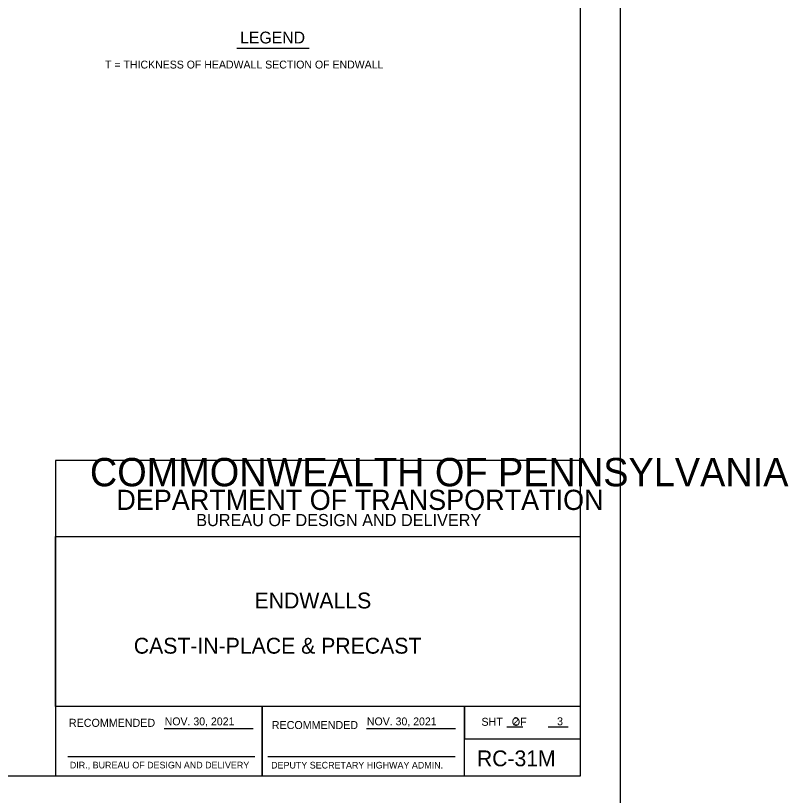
# Model space of a CAD drawing. Extents: x 638877 to 639960, y 297341 to 299123.
# Drawn here: x 639488 to 639782.3, y 297942.8 to 298239.6 of the extents above; entities that cross this region are included whole.
import ezdxf

# ---------------------------------------------------------------- set-up
doc = ezdxf.new("R2010")
doc.units = 0
for name, color, linetype in [('1', 7, 'Continuous'), ('2', 7, 'Continuous'), ('3', 7, 'Continuous'), ('PLT-BNDY', 7, 'Continuous')]:
    doc.layers.add(name, color=color, linetype=linetype)

msp = doc.modelspace()

# ---------------------------------------------------------------- linework, layer by layer
at = {"layer": '1'}
for p, q in [((639703.19, 297950.28), (639703.19, 298514.28)), ((639572.29, 298227.14), (639599.84, 298227.14)), ((639703.19, 298070.28), (639503.19, 298070.28)), ((639503.19, 298070.28), (639503.19, 297950.28)), ((639703.19, 298041.32), (639703.19, 298070.28)), ((639503.19, 297976.64), (639503.19, 298041.32)), ((639503.19, 298041.32), (639703.19, 298041.32)), ((639703.19, 297976.64), (639503.19, 297976.64)), ((639581.99, 297950.28), (639581.99, 297976.64)), ((639581.99, 297976.64), (639581.99, 297950.28)), ((639658.99, 297950.28), (639658.99, 297976.64)), ((639658.99, 297976.64), (639658.99, 297964.33)), ((639703.19, 297950.28), (639703.19, 297976.64)), ((639544.65, 297968.27), (639578.54, 297968.27)), ((639621.65, 297968.27), (639655.52, 297968.27)), ((639675.05, 297968.82), (639681.2, 297968.82)), ((639690.86, 297968.82), (639698.51, 297968.82)), ((639658.99, 297964.33), (639703.19, 297964.33)), ((639507.95, 297957.61), (639579.2, 297957.61)), ((639584.12, 297957.61), (639655.46, 297957.61)), ((638917.19, 297950.28), (639703.19, 297950.28))]:
    msp.add_line(p, q, dxfattribs=at)
at = {"layer": 'PLT-BNDY'}
msp.add_lwpolyline([(638877.19, 298529.28), (639718.19, 298529.28), (639718.19, 297935.28), (638877.19, 297935.28)], close=True, dxfattribs=at)

# ---------------------------------------------------------------- texts
at = {"layer": '1'}
for s, height, p in [('COMMONWEALTH OF PENNSYLVANIA', 10.7834, (639516.34, 298060.43)), ('DEPARTMENT OF TRANSPORTATION', 7.6843, (639526.4, 298051.43)), ('BUREAU OF DESIGN AND DELIVERY', 4.6221, (639556.83, 298045.27)), ('ENDWALLS', 6.04, (639579.04, 298013.94)), ('CAST-IN-PLACE & PRECAST', 6.04, (639533.05, 297996.73)), ('RECOMMENDED', 3.048, (639508.35, 297968.88)), ('NOV. 30, 2021', 3, (639544.82, 297969.45)), ('RECOMMENDED', 3.048, (639585.6, 297968.04)), ('NOV. 30, 2021', 3, (639621.82, 297969.45)), ('SHT   OF', 3.048, (639665.44, 297969.28)), ('APPROVED', 0.0192, (639546.21, 297968.22)), ('RC-31M', 6.016, (639663.72, 297953.87)), ('DIR., BUREAU OF DESIGN AND DELIVERY', 2.54, (639508.7, 297953.05)), ('DEPUTY SECRETARY HIGHWAY ADMIN.', 2.54, (639585.34, 297953.02))]:
    msp.add_text(s, height=height, dxfattribs=at).set_placement(p)
at = {"layer": '2'}
for s, p in [('2', (639677.39, 297969.49)), ('3', (639694.21, 297969.47))]:
    msp.add_text(s, height=3.05, dxfattribs=at).set_placement(p)
at = {"layer": '3'}
for s, height, p in [('LEGEND', 4.5, (639573.52, 298228.98)), ('T = THICKNESS OF HEADWALL SECTION OF ENDWALL', 2.9999, (639522.12, 298219.45))]:
    msp.add_text(s, height=height, dxfattribs=at).set_placement(p)

doc.saveas('drawing.dxf')
